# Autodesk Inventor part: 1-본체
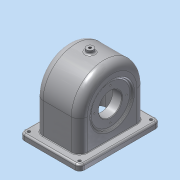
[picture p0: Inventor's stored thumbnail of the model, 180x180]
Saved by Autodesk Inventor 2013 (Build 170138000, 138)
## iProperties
Created: 2016-01
Part Number: 1-본체
Material: 알루미늄 6061
Document SubType Name: Modeling
Designer: dgall
Density: 1 g/cm^3
Author: dgall
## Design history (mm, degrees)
sketch "스케치1"
  geometry: L1 (-52, 70)-(52, 70); L2 (52, 70)-(52, -70); L3 (52, -70)-(-52, -70); L4 (-52, -70)-(-52, 70); 3 further points
  constraints: 8 end point, 2 midpoint, 2 parallel, 1 horizontal, 1 horizontal alignment, 1 perpendicular, 1 vertical alignment
  dimensions: "d0" = 104 distance of L1.start L1.end; "d2" = 140 distance of L1.end L2.end
extrude "돌출1" new body sketch "스케치1" distance "d3" = 10; taper "d4" = 0 deg
node "작업 평면1"
sketch "스케치2"
  geometry: L1 (0, 0)-(0, 140) reference; L2 (-10, 140)-(0, 140) reference; L3 (0, 140)-(0, 0) reference; L4 (0, 0)-(-10, 0) reference; L5 (-10, 0)-(-10, 140) reference; L6 (-64, 13)-(-10, 13); L7 (-64, 127)-(-10, 127); L8 (0, 19)-(-64, 19); L9 (-64, 121)-(0, 121); A1 r 57 centre (-64, 70) between (-64, 127) and (-64, 13); A2 r 51 centre (-64, 70) between (-64, 121) and (-64, 19); 1 further point
  constraints: 8 end point, 4 point on circle, 4 point on line, 2 centre point, 2 perpendicular, 2 tangent, 1 horizontal alignment, 1 parallel
  dimensions: "d5" = 57 radius of A1; "d6" = 64 distance from line of L1 A1.centre; "d7" = 6 distance between parallel lines of L7 L9; "d8" = 6 radial gap between concentric circles of A1 A2; "d9" = 6 distance between parallel lines of L6 L8
  node "절단 모서리 투영1"
extrude "돌출2" join sketch "스케치2" stored distance "d10" = 77; taper "d11" = 0 deg
extrude "돌출3" cut sketch "스케치2" stored distance "d12" = 67; taper "d13" = 0 deg
node "작업 평면2"
node "작업 평면3"
node "작업 평면4"
node "작업 평면5"
node "작업 평면7"
node "작업 평면8"
node "작업 평면9"
node "작업 평면10"
sketch "스케치10"
  geometry: L1 (0, 0)-(0, 140) reference; C1 r 31 at (60, 70); 2 further points
  constraints: 1 centre point, 1 horizontal alignment, 1 midpoint
  dimensions: "d53" = 62 diameter of C1; "d54" = 60 distance from line of L1 C1.centre
extrude "돌출8" join sketch "스케치10" distance "d55" = 10; taper "d56" = 0 deg
node "작업 평면11"
sketch "스케치11"
  geometry: L1 (77, 54)-(77, -57) reference; L2 (77, -57)-(0, -57) reference; L3 (0, -57)-(0, -27) reference; L4 (0, -27)-(-10, -27) reference; L5 (-10, -27)-(-10, 35) reference; L6 (-10, 35)-(0, 35) reference; L7 (0, 35)-(0, 54) reference; L8 (0, 54)-(-13.5, 54) reference; L9 (-13.5, 54)-(-13.5, 64) reference; L10 (-13.5, 64)-(5, 64) reference; L11 (5, 64)-(5, -51) reference; L12 (5, -51)-(72, -51) reference; L13 (72, -51)-(72, 64) reference; L14 (72, 64)-(90.5, 64) reference; L15 (90.5, 64)-(90.5, 54) reference; L16 (90.5, 54)-(77, 54) reference; L17 (-10, 4)-(77, 4); L18 (77, -39.943)-(58, -24); L19 (58, -24)-(58, 4); 1 further point
  constraints: 6 end point, 3 point on line, 2 perpendicular, 1 midpoint
  dimensions: "d57" = 50 deg angle of L19 L18; "d58" = 56 diameter of L18.end L17; "d60" = 19 distance between parallel lines of L1 L19
revolve "회전3" sketch "스케치11" stored, may be unused: angle "d61" = 90 deg
node "작업 평면12"
node "작업 평면13"
sketch "스케치12"
  geometry: L1 (-10, 13)-(-64, 13) reference; L2 (-64, 127)-(-10, 127) reference; L3 (-10, 127)-(-10, 140) reference; L4 (-10, 140)-(0, 140) reference; L5 (0, 140)-(0, 121) reference; L6 (0, 121)-(-64, 121) reference; L7 (-64, 19)-(0, 19) reference; L8 (0, 19)-(0, 0) reference; L9 (0, 0)-(-10, 0) reference; L10 (-10, 0)-(-10, 13) reference; C1 r 28 at (-60, 70); A1 r 57 centre (-64, 70) between (-64, 127) and (-64, 13) reference; A2 r 51 centre (-64, 70) between (-64, 121) and (-64, 19) reference; 1 further point
  constraints: 1 centre point, 1 horizontal alignment
  dimensions: "d64" = 56 diameter of C1; "d66" = 60 distance from line of L5 C1.centre
extrude "돌출9" join sketch "스케치12" stored distance "d67" = 10; taper "d68" = 40 deg
node "작업 평면14"
sketch "스케치13"
  geometry: L1 (5, 64)-(5, -51) reference; L2 (5, -51)-(72, -51) reference; L3 (72, -51)-(72, -35.747) reference; L4 (72, -35.747)-(58, -24) reference; L5 (58, -24)-(58, 32) reference; L6 (58, 32)-(72, 43.747) reference; L7 (72, 43.747)-(72, 64) reference; L8 (72, 64)-(90.5, 64) reference; L9 (90.5, 64)-(90.5, 54) reference; L10 (90.5, 54)-(77, 54) reference; L11 (77, 54)-(77, 47.943) reference; L12 (77, 47.943)-(74, 45.426) reference; L13 (74, 45.426)-(74, -37.426) reference; L14 (74, -37.426)-(77, -39.943) reference; L15 (77, -39.943)-(77, -57) reference; L16 (77, -57)-(0, -57) reference; L17 (0, -57)-(0, -27) reference; L18 (0, -27)-(-10, -27) reference; L19 (-10, -27)-(-10, 35) reference; L20 (-10, 35)-(0, 35) reference; L21 (0, 35)-(0, 54) reference; L22 (0, 54)-(-13.5, 54) reference; L23 (-13.5, 54)-(-13.5, 64) reference; L24 (-13.5, 64)-(5, 64) reference; L25 (77, -33.416)-(58, -17.473); L26 (77, 47.943)-(77, -39.943) reference; L27 (77, 4)-(-10, 4); L28 (5, 64)-(72, 64) reference; L29 (77, -33.416)-(77, -39.943); L30 (58, -24)-(77, -39.943); L31 (58, -24)-(58, -17.473); 1 further point
  constraints: 10 end point, 2 midpoint, 2 perpendicular, 2 point on line, 1 collinear, 1 parallel
  dimensions: "d69" = 5 distance between parallel lines of L14 L25; "d70" = 60 distance between parallel lines of L28 L27
revolve "회전4" sketch "스케치13" stored, may be unused: angle "d71" = 90 deg
sketch "스케치14"
  geometry: C1 r 31 at (0, 0) reference; C2 r 20 at (0, 0); 1 further point
  constraints: 1 centre point, 1 coincident
  dimensions: "d72" = 40 diameter of C2
extrude "돌출10" cut sketch "스케치14" stored distance "d73" = 10; taper "d74" = 0 deg
sketch "스케치15"
  geometry: C1 r 20 at (0, 0) reference; C2 r 31 at (0, 0) reference; A1 r 24 centre (0, 0) between (24, 0) and (0, 24); 3 further points
  constraints: 4 point on circle, 2 horizontal alignment, 2 vertical alignment, 1 centre point, 1 coincident
  dimensions: "d75" = 48 diameter of A1
hole "구멍1" sketch "스케치15" at (24, 0), (0, 24), (0, -24), (-24, 0) diameter "d76" = 2.459; stored, may be unused: countersink angle "d80" = 90 deg, drill point angle "d82" = 118 deg; dims "d77" = 6, "d78" = 4, "d79" = 2, "d81" = 8
sketch "스케치16"
  geometry: C1 r 20 at (0, 0) reference; C2 r 34.899 at (0, 0) reference; A1 r 28 centre (0, 0) between (-28, 0) and (28, 0); 3 further points
  constraints: 4 point on circle, 2 horizontal alignment, 2 vertical alignment, 1 centre point, 1 coincident
  dimensions: "d83" = 56 diameter of A1
hole "구멍2" sketch "스케치16" at (-28, 0), (28, 0), (0, -28), (0, 28) diameter "d84" = 2.459; stored, may be unused: countersink angle "d88" = 90 deg, drill point angle "d90" = 118 deg; dims "d85" = 7, "d86" = 4, "d87" = 2, "d89" = 9
node "작업 평면15"
sketch "스케치17"
  geometry: C1 r 6 at (0, 0); 1 further point
  constraints: 1 centre point, 1 coincident
  dimensions: "d92" = 12 diameter of C1
extrude "돌출11" join sketch "스케치17" stored distance "d93" = 10; taper "d94" = 0 deg
hole "구멍3" diameter "d97" = 4.459; stored, may be unused: countersink angle "d101" = 90 deg, drill point angle "d103" = 118 deg; dims "d95" = 10, "d96" = 10, "d98" = 7, "d99" = 4, "d100" = 2, "d102" = 9
fillet "모깎기1" dims "d104" = 9
fillet "모깎기2" dims "d105" = 14
fillet "모깎기3" dims "d106" = 3
chamfer "모따기1" distance "d107" = 1; stored, may be unused: second distance "d108" = 2, angle "d109" = 45 deg
fillet "모깎기4" dims "d110" = 8
sketch "스케치18"
  geometry: C1 r 2.5 at (-44, 62); C2 r 2.5 at (44, 62); C3 r 2.5 at (44, -62); C4 r 2.5 at (-44, -62); A1 r 8 centre (-44, -62) between (-52, -62) and (-44, -70) reference; A2 r 8 centre (44, -62) between (44, -70) and (52, -62) reference; A3 r 8 centre (44, 62) between (52, 62) and (44, 70) reference; A4 r 8 centre (-44, 62) between (-44, 70) and (-52, 62) reference; 1 further point
  constraints: 4 centre point, 4 coincident, 3 equal radius
  dimensions: "d111" = 5 diameter of C1
extrude "돌출12" cut sketch "스케치18" stored distance "d113" = 10; taper "d114" = 0 deg
fillet "모깎기5" dims "d115" = 3
fillet "모깎기6" dims "d116" = 1
sketch "스케치19"
  geometry: L1 (-19.5, 64)-(68.5, 64) reference; L2 (63, 0)-(63, 53) reference; 2 further points
  constraints: 1 other
  dimensions: "d117" = 30 distance from line of L1 point (24.5, 34); "d118" = 38.5 distance from line of L2 point (24.5, 34)
feature "엠보싱1" sketch "스케치19" dims "d5" = 57, "d6" = 64, "d7" = 6, "d8" = 6, "d9" = 6, "d119" = 0.5, "d120" = 0
fillet "모깎기7" dims "d121" = 3
node "솔리드1"
node "절단 모서리 투영4"
node "절단 모서리 투영5"
node "절단 모서리 투영6"
other parameters: "d27" = -19, "d46" = -3, "d47" = -19, "d48" = -3, "d49" = -19, "d62" = -3, "d63" = -19, "d91" = -127
